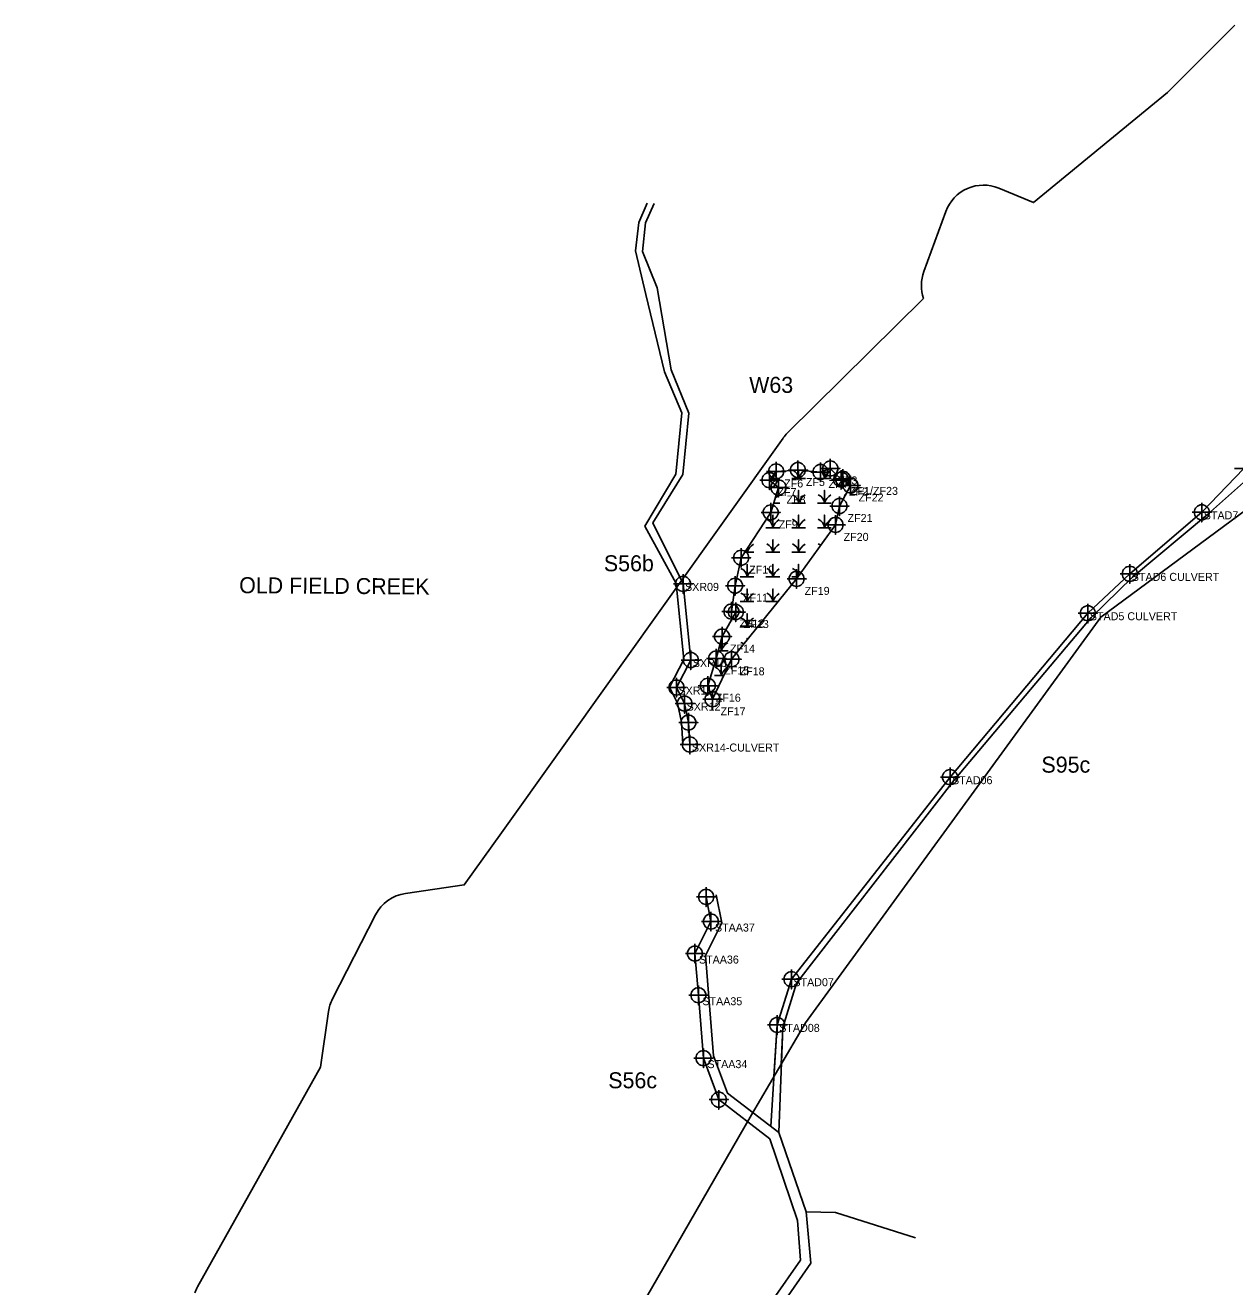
# Model space of a CAD drawing. Extents: x 1253697 to 1278588, y 912189 to 981699.
# Drawn here: x 1254767 to 1256277, y 956813 to 958390 of the extents above; entities that cross this region are included whole.
import ezdxf

# ---------------------------------------------------------------- set-up
doc = ezdxf.new("R2010")
doc.units = 0
for name, color, linetype in [('Default', 7, 'Continuous'), ('Exist Environmental Wetland Boundary', 7, 'Continuous'), ('Exist Environmental Wetland Boundary Cogo Comment', 7, 'Continuous'), ('Exist Environmental Wetland Boundary Cogo Number', 7, 'Continuous'), ('Exist Environmental Wetland Boundary Cogo Point CELL', 7, 'Continuous'), ('Exist Hydro Jurisdictional Stream or Body of Water Mitigable', 7, 'Continuous'), ('Exist Hydro Jurisdictional Stream or Body of Water Mitigable Cogo Comment', 7, 'Continuous'), ('Exist Hydro Jurisdictional Stream or Body of Water Mitigable Cogo Number', 7, 'Continuous'), ('Exist Hydro Jurisdictional Stream or Body of Water Mitigable Cogo Point CELL', 7, 'Continuous'), ('Exist Hydro Swamp or Marsh', 7, 'Continuous')]:
    doc.layers.add(name, color=color, linetype=linetype)

msp = doc.modelspace()

# ---------------------------------------------------------------- linework, layer by layer
at = {"layer": 'Default'}
for p, q in [((1255916.6, 958157.4), (1255889.1, 958082.1)), ((1255916.6, 958157.4), (1255889.1, 958082.1)), ((1255888.9, 958048.4), (1255718.7, 957880.5)), ((1255888.9, 958048.4), (1255718.7, 957880.5)), ((1255204.3, 957278.2), (1255150.4, 957173.1)), ((1255204.3, 957278.2), (1255150.4, 957173.1))]:
    msp.add_line(p, q, dxfattribs=at)
for points in [[(1256277.5, 958390), (1256193.5, 958305.9), (1256026.3, 958168.4), (1255982.7, 958186.4)], [(1256277.5, 958390), (1256193.5, 958305.9), (1256026.3, 958168.4), (1255982.7, 958186.4)], [(1255713.2, 957873.9), (1255361.7, 957380.8), (1255315.1, 957315.4), (1255241.7, 957304.9)], [(1255713.2, 957873.9), (1255361.7, 957380.8), (1255315.1, 957315.4), (1255241.7, 957304.9)], [(1255510.9, 956745.4), (1255673.9, 957028.1), (1255741.4, 957143.3), (1256110.4, 957650.3), (1256378.3, 957848.6)], [(1255510.9, 956745.4), (1255673.9, 957028.1), (1255741.4, 957143.3), (1256110.4, 957650.3), (1256378.3, 957848.6)], [(1255145.4, 957157.3), (1255135.4, 957087.6), (1254982, 956813.2)], [(1255145.4, 957157.3), (1255135.4, 957087.6), (1254982, 956813.2)]]:
    msp.add_lwpolyline(points, dxfattribs=at)
for centre, start, end in [((1255963.6, 958140.2), 67.5655, 159.9291), ((1255963.6, 958140.2), 67.5655, 159.9291), ((1255936.1, 958064.9), 159.9291, 199.2414), ((1255936.1, 958064.9), 159.9291, 199.2414), ((1255753.9, 957844.9), 134.6381, 144.5225), ((1255753.9, 957844.9), 134.6381, 144.5225), ((1255248.8, 957255.4), 98.1248, 152.8655), ((1255248.8, 957255.4), 98.1248, 152.8655), ((1255194.9, 957150.2), 152.8655, 171.8889), ((1255194.9, 957150.2), 152.8655, 171.8889), ((1255025.6, 956788.8), 150.7821, 160.1328), ((1255025.6, 956788.8), 150.7821, 160.1328)]:
    msp.add_arc(centre, 50, start, end, dxfattribs=at)
at = {"layer": 'Exist Environmental Wetland Boundary'}
msp.add_lwpolyline([(1255788.1, 957823), (1255785.7, 957822.1), (1255772.3, 957836), (1255760, 957831.6), (1255731.8, 957834.1), (1255704.6, 957832.3), (1255696.2, 957821.4), (1255707.6, 957812.2), (1255697.8, 957781.1), (1255660.9, 957724.5), (1255653.3, 957689.5), (1255648.7, 957657.2), (1255654.2, 957656.6), (1255637, 957625.9), (1255629.8, 957598.5), (1255619.2, 957564.5), (1255625.2, 957547.5), (1255649, 957597.5), (1255730.2, 957698), (1255778.9, 957765.5), (1255783.8, 957789.1), (1255797.6, 957814.8)], close=True, dxfattribs=at)
at = {"layer": 'Exist Environmental Wetland Boundary Cogo Point CELL'}
for points in [[(1255704.6, 957844.3), (1255704.6, 957820.3), (1255704.6, 957832.3), (1255716.6, 957832.3), (1255692.6, 957832.3)], [(1255731.8, 957846.1), (1255731.8, 957822.1), (1255731.8, 957834.1), (1255743.8, 957834.1), (1255719.8, 957834.1)], [(1255760, 957843.6), (1255760, 957819.6), (1255760, 957831.6), (1255772, 957831.6), (1255748, 957831.6)], [(1255772.3, 957848), (1255772.3, 957824), (1255772.3, 957836), (1255784.3, 957836), (1255760.3, 957836)], [(1255696.2, 957833.4), (1255696.2, 957809.4), (1255696.2, 957821.4), (1255708.2, 957821.4), (1255684.2, 957821.4)], [(1255785.7, 957834.1), (1255785.7, 957810.1), (1255785.7, 957822.1), (1255797.7, 957822.1), (1255773.7, 957822.1)], [(1255788.1, 957835), (1255788.1, 957811), (1255788.1, 957823), (1255800.1, 957823), (1255776.1, 957823)], [(1255797.6, 957826.8), (1255797.6, 957802.8), (1255797.6, 957814.8), (1255809.6, 957814.8), (1255785.6, 957814.8)], [(1255707.6, 957824.2), (1255707.6, 957800.2), (1255707.6, 957812.2), (1255719.6, 957812.2), (1255695.6, 957812.2)], [(1255783.8, 957801.1), (1255783.8, 957777.1), (1255783.8, 957789.1), (1255795.8, 957789.1), (1255771.8, 957789.1)], [(1255697.8, 957793.1), (1255697.8, 957769.1), (1255697.8, 957781.1), (1255709.8, 957781.1), (1255685.8, 957781.1)], [(1255778.9, 957777.5), (1255778.9, 957753.5), (1255778.9, 957765.5), (1255790.9, 957765.5), (1255766.9, 957765.5)], [(1255660.9, 957736.5), (1255660.9, 957712.5), (1255660.9, 957724.5), (1255672.9, 957724.5), (1255648.9, 957724.5)], [(1255653.3, 957701.5), (1255653.3, 957677.5), (1255653.3, 957689.5), (1255665.3, 957689.5), (1255641.3, 957689.5)], [(1255730.2, 957710), (1255730.2, 957686), (1255730.2, 957698), (1255742.2, 957698), (1255718.2, 957698)], [(1255648.7, 957669.2), (1255648.7, 957645.2), (1255648.7, 957657.2), (1255660.7, 957657.2), (1255636.7, 957657.2)], [(1255654.2, 957668.6), (1255654.2, 957644.6), (1255654.2, 957656.6), (1255666.2, 957656.6), (1255642.2, 957656.6)], [(1255637, 957637.9), (1255637, 957613.9), (1255637, 957625.9), (1255649, 957625.9), (1255625, 957625.9)], [(1255629.8, 957610.5), (1255629.8, 957586.5), (1255629.8, 957598.5), (1255641.8, 957598.5), (1255617.8, 957598.5)], [(1255649, 957609.5), (1255649, 957585.5), (1255649, 957597.5), (1255661, 957597.5), (1255637, 957597.5)], [(1255619.2, 957576.5), (1255619.2, 957552.5), (1255619.2, 957564.5), (1255631.2, 957564.5), (1255607.2, 957564.5)], [(1255625.2, 957559.5), (1255625.2, 957535.5), (1255625.2, 957547.5), (1255637.2, 957547.5), (1255613.2, 957547.5)]]:
    msp.add_lwpolyline(points, dxfattribs=at)
for centre in [(1255731.8, 957834.1), (1255772.3, 957836), (1255696.2, 957821.4), (1255704.6, 957832.3), (1255760, 957831.6), (1255785.7, 957822.1), (1255788.1, 957823), (1255707.6, 957812.2), (1255797.6, 957814.8), (1255783.8, 957789.1), (1255697.8, 957781.1), (1255778.9, 957765.5), (1255660.9, 957724.5), (1255730.2, 957698), (1255653.3, 957689.5), (1255648.7, 957657.2), (1255654.2, 957656.6), (1255637, 957625.9), (1255629.8, 957598.5), (1255649, 957597.5), (1255619.2, 957564.5), (1255625.2, 957547.5)]:
    msp.add_circle(centre, 9.38, dxfattribs=at)
at = {"layer": 'Exist Hydro Jurisdictional Stream or Body of Water Mitigable'}
for p, q in [((1255706, 957140.5), (1255697.9, 957013.5)), ((1255712.8, 957137.4), (1255707.8, 957005.9))]:
    msp.add_line(p, q, dxfattribs=at)
for points in [[(1255588.2, 957491.5), (1255586.4, 957518.9), (1255581.6, 957542.7), (1255571.5, 957562.7), (1255589.4, 957597.1), (1255579.6, 957692.3), (1255540.6, 957763.9), (1255579.3, 957829.1), (1255586.7, 957905.5), (1255565.3, 957956.9), (1255542, 958053.5), (1255528.9, 958107.9), (1255532.9, 958143.6), (1255543.4, 958167.8)], [(1255596.9, 957491), (1255595, 957518.4), (1255590.3, 957542.1), (1255580.2, 957562.2), (1255598, 957596.6), (1255588.3, 957691.8), (1255550.7, 957768.2), (1255587.9, 957828.5), (1255595.4, 957905), (1255573.6, 957959.3), (1255556, 958061.6), (1255537.6, 958107.4), (1255541.6, 958143), (1255552.1, 958167.3)], [(1255701.8, 957075.9), (1255706, 957140.5), (1255723.7, 957197.6), (1255921.8, 957450.2), (1256094, 957655), (1256146.4, 957704.3), (1256236.3, 957781.2), (1256289, 957836.1), (1256289, 957836.1), (1256289, 957836.1), (1256289, 957836.1)], [(1255711.1, 957091.6), (1255712.8, 957137.4), (1255730, 957192.6), (1255926.4, 957446.2), (1256098.3, 957649.6), (1256149.6, 957700), (1256243.3, 957778.4), (1256303.3, 957831.9), (1256303.3, 957831.9)], [(1255633, 957047.1), (1255613.8, 957099), (1255607.5, 957177.6), (1255603.2, 957229.7), (1255623.2, 957269.7), (1255617.2, 957300.5)], [(1255707.8, 957005.9), (1255643.8, 957055.1), (1255626.5, 957101.8), (1255616.3, 957227.2), (1255636.6, 957267.9), (1255629.8, 957302.9)], [(1254773.7, 955356), (1254812.6, 955366.4), (1254874.8, 955427.8), (1254955.3, 955516.3), (1255019.8, 955557.3), (1255064.3, 955601), (1255149.3, 955731.4), (1255209.5, 955843), (1255222.6, 955926.9), (1255346.2, 956050.2), (1255419.1, 956093.7), (1255471.8, 956221.8), (1255479.5, 956338.2), (1255514.4, 956421.9), (1255531.6, 956428.8), (1255553.6, 956479.5), (1255609.2, 956591), (1255636.4, 956630.9), (1255675.4, 956719.4), (1255701.3, 956798.3), (1255734.9, 956846.5), (1255731.5, 956896), (1255696.9, 956998.1), (1255633, 957047.1)], [(1255707.8, 957005.9), (1255707.8, 957005.9), (1255742.1, 956907), (1255748, 956842.8), (1255713, 956792.5), (1255687.4, 956714.8), (1255647.7, 956624.7), (1255620.3, 956584.5), (1255565.2, 956474.1), (1255541.3, 956418.8), (1255524.2, 956412), (1255492.1, 956335.2), (1255484.5, 956218.8), (1255429.3, 956084.8), (1255354.1, 956039.9), (1255234.6, 955920.8), (1255221.8, 955838.8), (1255160.3, 955724.8), (1255070.2, 955596.4), (1255027.9, 955547.1), (1254960.3, 955508.8), (1254884, 955418.9), (1254819.1, 955354.8), (1254766.6, 955341.9)], [(1255742.1, 956907), (1255778.7, 956906.2), (1255878.5, 956874.2)]]:
    msp.add_lwpolyline(points, dxfattribs=at)
at = {"layer": 'Exist Hydro Jurisdictional Stream or Body of Water Mitigable Cogo Point CELL'}
for points in [[(1256289, 957848.1), (1256289, 957824.1), (1256289, 957836.1), (1256301, 957836.1), (1256277, 957836.1)], [(1256236.3, 957793.2), (1256236.3, 957769.2), (1256236.3, 957781.2), (1256248.3, 957781.2), (1256224.3, 957781.2)], [(1256146.4, 957716.3), (1256146.4, 957692.3), (1256146.4, 957704.3), (1256158.4, 957704.3), (1256134.4, 957704.3)], [(1255588.3, 957703.8), (1255588.3, 957679.8), (1255588.3, 957691.8), (1255600.3, 957691.8), (1255576.3, 957691.8)], [(1256094, 957667), (1256094, 957643), (1256094, 957655), (1256106, 957655), (1256082, 957655)], [(1255598, 957608.6), (1255598, 957584.6), (1255598, 957596.6), (1255610, 957596.6), (1255586, 957596.6)], [(1255580.2, 957574.2), (1255580.2, 957550.2), (1255580.2, 957562.2), (1255592.2, 957562.2), (1255568.2, 957562.2)], [(1255590.3, 957554.1), (1255590.3, 957530.1), (1255590.3, 957542.1), (1255602.3, 957542.1), (1255578.3, 957542.1)], [(1255595, 957530.4), (1255595, 957506.4), (1255595, 957518.4), (1255607, 957518.4), (1255583, 957518.4)], [(1255596.9, 957503), (1255596.9, 957479), (1255596.9, 957491), (1255608.9, 957491), (1255584.9, 957491)], [(1255921.8, 957462.2), (1255921.8, 957438.2), (1255921.8, 957450.2), (1255933.8, 957450.2), (1255909.8, 957450.2)], [(1255617.2, 957312.5), (1255617.2, 957288.5), (1255617.2, 957300.5), (1255629.2, 957300.5), (1255605.2, 957300.5)], [(1255623.2, 957281.7), (1255623.2, 957257.7), (1255623.2, 957269.7), (1255635.2, 957269.7), (1255611.2, 957269.7)], [(1255603.2, 957241.7), (1255603.2, 957217.7), (1255603.2, 957229.7), (1255615.2, 957229.7), (1255591.2, 957229.7)], [(1255723.7, 957209.6), (1255723.7, 957185.6), (1255723.7, 957197.6), (1255735.7, 957197.6), (1255711.7, 957197.6)], [(1255607.5, 957189.6), (1255607.5, 957165.6), (1255607.5, 957177.6), (1255619.5, 957177.6), (1255595.5, 957177.6)], [(1255706, 957152.5), (1255706, 957128.5), (1255706, 957140.5), (1255718, 957140.5), (1255694, 957140.5)], [(1255613.8, 957111), (1255613.8, 957087), (1255613.8, 957099), (1255625.8, 957099), (1255601.8, 957099)], [(1255633, 957059.1), (1255633, 957035.1), (1255633, 957047.1), (1255645, 957047.1), (1255621, 957047.1)]]:
    msp.add_lwpolyline(points, dxfattribs=at)
for centre in [(1256236.3, 957781.2), (1255588.3, 957691.8), (1256146.4, 957704.3), (1256094, 957655), (1255598, 957596.6), (1255580.2, 957562.2), (1255590.3, 957542.1), (1255595, 957518.4), (1255596.9, 957491), (1255921.8, 957450.2), (1255617.2, 957300.5), (1255623.2, 957269.7), (1255603.2, 957229.7), (1255723.7, 957197.6), (1255607.5, 957177.6), (1255706, 957140.5), (1255613.8, 957099), (1255633, 957047.1)]:
    msp.add_circle(centre, 9.38, dxfattribs=at)
at = {"layer": 'Exist Hydro Swamp or Marsh'}
for p, q in [((1255701.5, 957792.7), (1255709.1, 957792.7)), ((1255724.1, 957700.4), (1255732, 957700.4)), ((1255644.2, 957638.8), (1255644.7, 957638.8))]:
    msp.add_line(p, q, dxfattribs=at)
for points in [[(1255697.8, 957823.5), (1255700.5, 957823.5), (1255700.5, 957827)], [(1255700.5, 957827), (1255700.5, 957823.5), (1255709.1, 957823.5)], [(1255724.1, 957823.5), (1255732.7, 957823.5), (1255732.7, 957834)], [(1255732.7, 957834), (1255732.7, 957823.5), (1255741.3, 957823.5)], [(1255756.3, 957823.5), (1255764.9, 957823.5), (1255764.9, 957833.3)], [(1255764.9, 957833.3), (1255764.9, 957823.5), (1255773.5, 957823.5)], [(1255724.1, 957792.7), (1255732.7, 957792.7), (1255732.7, 957808.5), (1255732.7, 957792.7), (1255741.3, 957792.7)], [(1255756.3, 957792.7), (1255764.9, 957792.7), (1255764.9, 957808.5), (1255764.9, 957792.7), (1255773.5, 957792.7)], [(1255691.9, 957762), (1255700.5, 957762), (1255700.5, 957777.7), (1255700.5, 957762), (1255709.1, 957762)], [(1255724.1, 957762), (1255732.7, 957762), (1255732.7, 957777.7), (1255732.7, 957762), (1255741.3, 957762)], [(1255756.3, 957762), (1255764.9, 957762), (1255764.9, 957777.7), (1255764.9, 957762), (1255773.5, 957762)], [(1255665.3, 957731.2), (1255668.3, 957731.2), (1255668.3, 957735.8)], [(1255668.3, 957735.8), (1255668.3, 957731.2), (1255676.9, 957731.2)], [(1255691.9, 957731.2), (1255700.5, 957731.2), (1255700.5, 957747), (1255700.5, 957731.2), (1255709.1, 957731.2)], [(1255724.1, 957731.2), (1255732.7, 957731.2), (1255732.7, 957747), (1255732.7, 957731.2), (1255741.3, 957731.2)], [(1255764.9, 957746.1), (1255764.9, 957747), (1255764.9, 957746.1)], [(1255659.7, 957700.4), (1255668.3, 957700.4), (1255668.3, 957716.2), (1255668.3, 957700.4), (1255676.9, 957700.4)], [(1255691.9, 957700.4), (1255700.5, 957700.4), (1255700.5, 957716.2), (1255700.5, 957700.4), (1255709.1, 957700.4)], [(1255732.7, 957701.4), (1255732.7, 957716.2), (1255732.7, 957701.4)], [(1255659.7, 957669.6), (1255668.3, 957669.6), (1255668.3, 957685.4), (1255668.3, 957669.6), (1255676.9, 957669.6)], [(1255691.9, 957669.6), (1255700.5, 957669.6), (1255700.5, 957685.4), (1255700.5, 957669.6), (1255707.3, 957669.6)], [(1255659.7, 957638.8), (1255668.3, 957638.8), (1255668.3, 957654.6), (1255668.3, 957638.8), (1255676.9, 957638.8)], [(1255632.3, 957608), (1255636.1, 957608), (1255636.1, 957622.6)], [(1255636.1, 957622.6), (1255636.1, 957608), (1255644.7, 957608)], [(1255668.3, 957621.4), (1255668.3, 957623.8), (1255668.3, 957621.4)], [(1255627.5, 957577.3), (1255636.1, 957577.3), (1255636.1, 957593), (1255636.1, 957577.3), (1255639.4, 957577.3)]]:
    msp.add_lwpolyline(points, dxfattribs=at)
for centre, radius, start, end in [((1255688.2, 957822.6), 12.3, 4.1403, 17.5216), ((1255718.7, 957817.5), 19.2, 128.7609, 161.6222), ((1255720.4, 957822.6), 12.3, 4.1403, 64.3311), ((1255750.9, 957817.5), 19.2, 124.157, 161.6222), ((1255752.6, 957822.6), 12.3, 4.1403, 48.6437), ((1255783.2, 957817.5), 19.2, 122.1274, 161.6222), ((1255718.7, 957786.7), 19.2, 122.1274, 144.4563), ((1255720.4, 957791.8), 12.3, 4.1403, 67.535), ((1255750.9, 957786.7), 19.2, 122.1274, 161.6222), ((1255752.6, 957791.8), 12.3, 4.1403, 67.535), ((1255783.2, 957786.7), 19.2, 122.1274, 161.6222), ((1255784.8, 957791.8), 12.3, 60.1225, 67.535), ((1255688.2, 957761.1), 12.3, 4.1403, 67.535), ((1255718.7, 957755.9), 19.2, 122.1274, 161.6222), ((1255720.4, 957761.1), 12.3, 4.1403, 67.535), ((1255750.9, 957755.9), 19.2, 122.1274, 161.6222), ((1255752.6, 957761.1), 12.3, 4.1403, 67.535), ((1255783.2, 957755.9), 19.2, 122.1274, 161.6222), ((1255656, 957730.3), 12.3, 4.1403, 20.6785), ((1255686.5, 957725.1), 19.2, 122.1274, 161.6222), ((1255688.2, 957730.3), 12.3, 4.1403, 67.535), ((1255718.7, 957725.1), 19.2, 122.1274, 161.6222), ((1255720.4, 957730.3), 12.3, 4.1403, 67.535), ((1255750.9, 957725.1), 19.2, 122.1274, 161.6222), ((1255752.6, 957730.3), 12.3, 51.0401, 67.535), ((1255656, 957699.5), 12.3, 4.1403, 67.535), ((1255686.5, 957694.3), 19.2, 122.1274, 161.6222), ((1255688.2, 957699.5), 12.3, 4.1403, 67.535), ((1255718.7, 957694.3), 19.2, 122.1274, 161.6222), ((1255720.4, 957699.5), 12.3, 8.3697, 67.535), ((1255750.9, 957694.3), 19.2, 134.6093, 153.8629), ((1255656, 957668.7), 12.3, 4.1403, 67.535), ((1255686.5, 957663.5), 19.2, 122.1274, 161.6222), ((1255688.2, 957668.7), 12.3, 4.1403, 67.535), ((1255718.7, 957663.5), 19.2, 122.1274, 161.6222), ((1255656, 957637.9), 12.3, 4.1403, 67.535), ((1255686.5, 957632.8), 19.2, 122.1274, 161.6222), ((1255623.8, 957607.2), 12.3, 4.1403, 34.9651), ((1255654.3, 957602), 19.2, 122.1274, 161.6222), ((1255656, 957607.2), 12.3, 48.2854, 67.535), ((1255623.8, 957576.4), 12.3, 4.1403, 67.535), ((1255654.3, 957571.2), 19.2, 122.1274, 161.6222), ((1255623.8, 957545.6), 12.3, 62.6012, 67.535)]:
    msp.add_arc(centre, radius, start, end, dxfattribs=at)

# ---------------------------------------------------------------- texts
at = {"layer": 'Exist Environmental Wetland Boundary Cogo Comment'}
for s, p in [('ZF3', (1255782.3, 957816)), ('ZF7', (1255706.2, 957801.4)), ('ZF6', (1255714.6, 957812.3)), ('ZF5', (1255741.8, 957814.1)), ('ZF4', (1255770, 957811.6)), ('ZF2', (1255795.7, 957802.1)), ('ZF1/ZF23', (1255798.1, 957803)), ('ZF8', (1255717.6, 957792.2)), ('ZF22', (1255807.6, 957794.8)), ('ZF21', (1255793.8, 957769.1)), ('ZF9', (1255707.8, 957761.1)), ('ZF20', (1255788.9, 957745.5)), ('ZF10', (1255670.9, 957704.5)), ('ZF19', (1255740.2, 957678)), ('ZF11', (1255663.3, 957669.5)), ('ZF12', (1255658.7, 957637.2)), ('ZF13', (1255664.2, 957636.6)), ('ZF14', (1255647, 957605.9)), ('ZF15', (1255639.8, 957578.5)), ('ZF18', (1255659, 957577.5)), ('ZF16', (1255629.2, 957544.5)), ('ZF17', (1255635.2, 957527.5))]:
    msp.add_text(s, height=10, dxfattribs=at).set_placement(p)
at = {"layer": 'Exist Environmental Wetland Boundary Cogo Number'}
msp.add_text('W63', height=20, dxfattribs=at).set_placement((1255670.9, 957930.5))
at = {"layer": 'Exist Hydro Jurisdictional Stream or Body of Water Mitigable Cogo Comment'}
for s, p in [('STAD7', (1256238.8, 957772.5)), ('STAD6 CULVERT', (1256148.9, 957695.5)), ('SXR09', (1255590.8, 957683)), ('STAD5 CULVERT', (1256096.5, 957646.3)), ('SXR10', (1255600.5, 957587.8)), ('SXR11', (1255582.7, 957553.4)), ('SXR12', (1255592.8, 957533.4)), ('SXR14-CULVERT', (1255599.4, 957482.2)), ('STAD06', (1255924.3, 957441.4)), ('STAA37', (1255628.2, 957257.2)), ('STAA36', (1255608.2, 957217.2)), ('STAD07', (1255726.2, 957188.9)), ('STAA35', (1255612.5, 957165.1)), ('STAD08', (1255708.5, 957131.8)), ('STAA34', (1255618.8, 957086.5))]:
    msp.add_text(s, height=10, dxfattribs=at).set_placement(p)
at = {"layer": 'Exist Hydro Jurisdictional Stream or Body of Water Mitigable Cogo Number'}
for s, p in [('S56b', (1255489.4, 957707.5)), ('S95c', (1256036, 957455.8)), ('S56c', (1255494.9, 957061.3))]:
    msp.add_text(s, height=20, dxfattribs=at).set_placement(p)
msp.add_text('OLD FIELD CREEK', height=20, rotation=359.5683, dxfattribs=at).set_placement((1255033.8, 957680.2))

doc.saveas('drawing.dxf')
